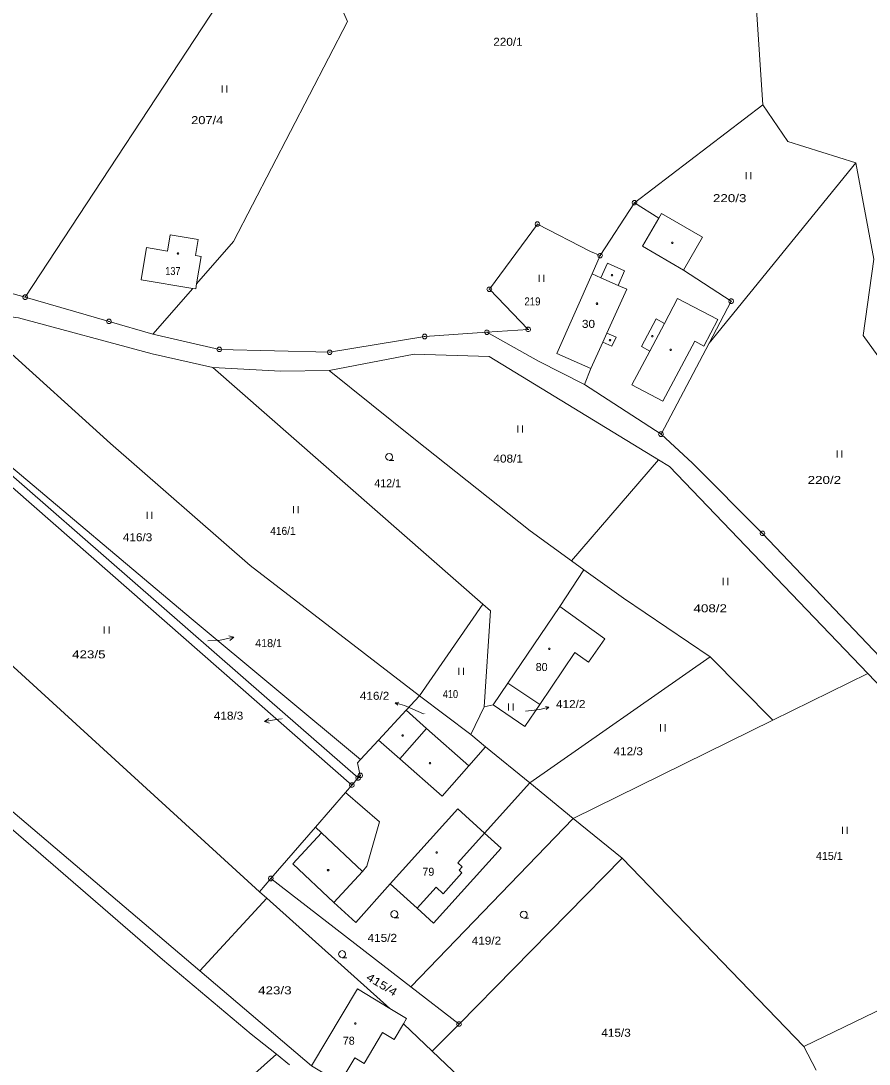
# Model space of a CAD drawing. Extents: x -687390 to -684106, y -954833 to -951648.
# Drawn here: x -686581.3 to -686401.1, y -952815.4 to -952593.8 of the extents above; entities that cross this region are included whole.
import ezdxf
from ezdxf.enums import TextEntityAlignment as Align

# ---------------------------------------------------------------- set-up
doc = ezdxf.new("R2010")
doc.units = 0
doc.header["$LTSCALE"] = 0.68
for name, color, linetype, lineweight in [('1', 7, 'Continuous', 13), ('3', 7, 'Continuous', 13), ('4', 7, 'Continuous', 13), ('5', 7, 'Continuous', 13), ('7', 7, 'Continuous', 13), ('8', 7, 'Continuous', 13)]:
    doc.layers.add(name, color=color, linetype=linetype, lineweight=lineweight)
doc.layers.add('2', color=7, linetype='Continuous')

msp = doc.modelspace()

# ---------------------------------------------------------------- linework, layer by layer
at = {"layer": '1'}
for p, q in [((-686425.13, -952590.27), (-686423.68, -952611.6)), ((-686458.26, -952643.63), (-686450.94, -952632.42)), ((-686445.81, -952635.7), (-686445.22, -952634.68)), ((-686543.98, -952649.65), (-686536.12, -952640.66)), ((-686544.81, -952650.6), (-686553.3, -952660.3)), ((-686580.4, -952652.47), (-686562.6, -952657.61)), ((-686553.3, -952660.3), (-686562.6, -952657.61)), ((-686585.59, -952662.44), (-686562.27, -952683.54)), ((-686435.12, -952662.25), (-686445.31, -952681.57)), ((-686613.19, -952664.18), (-686529.1, -952737.61)), ((-686612.84, -952663.77), (-686545.12, -952720.73)), ((-686540.52, -952667.43), (-686553.46, -952664.51)), ((-686471.33, -952666.06), (-686461.61, -952671.04)), ((-686540.52, -952667.43), (-686526.1, -952668.17)), ((-686515.83, -952668.02), (-686526.1, -952668.17)), ((-686497.82, -952682.47), (-686473.14, -952702.07)), ((-686445.31, -952681.57), (-686438.62, -952687.72)), ((-686532.63, -952709.42), (-686562.27, -952683.54)), ((-686464.34, -952708.44), (-686445.87, -952687)), ((-686423.77, -952702.62), (-686438.62, -952687.72)), ((-686532.63, -952709.42), (-686496.66, -952737.14)), ((-686483.17, -952717.66), (-686496.66, -952737.14)), ((-686466.81, -952718.15), (-686477.84, -952734.42)), ((-686434.87, -952728.81), (-686453.32, -952716.4)), ((-686509.16, -952750.64), (-686545.12, -952720.73)), ((-686530.65, -952778.73), (-686586.94, -952727.34)), ((-686473.17, -952755.63), (-686434.87, -952728.81)), ((-686434.87, -952728.81), (-686421.53, -952742.32)), ((-686480.99, -952739.06), (-686477.84, -952734.42)), ((-686477.84, -952734.42), (-686471.1, -952738.99)), ((-686529.1, -952737.61), (-686509.67, -952754.57)), ((-686496.66, -952737.14), (-686485.74, -952745.37)), ((-686480.99, -952739.06), (-686482.9, -952739.43)), ((-686480.99, -952739.06), (-686474.22, -952743.64)), ((-686471.1, -952738.99), (-686474.22, -952743.64)), ((-686482.58, -952747.94), (-686486.13, -952751.98)), ((-686509.16, -952750.64), (-686509.81, -952751.34)), ((-686509.81, -952751.34), (-686509.21, -952754.04)), ((-686473.17, -952755.63), (-686482.79, -952766.3)), ((-686473.17, -952755.63), (-686463.95, -952763.15)), ((-686518.73, -952765), (-686517.45, -952766.2)), ((-686482.79, -952766.3), (-686479.27, -952769.48)), ((-686488.24, -952806.85), (-686453.59, -952771.6)), ((-686528.22, -952775.93), (-686530.65, -952778.73)), ((-686502.9, -952777.04), (-686497.14, -952782.23)), ((-686543.29, -952795.55), (-686529.07, -952780.13)), ((-686551.22, -952793.14), (-686532.41, -952809.02)), ((-686509.81, -952799.39), (-686519.6, -952815.68)), ((-686502.94, -952803.52), (-686509.81, -952799.39)), ((-686499.36, -952805.67), (-686502.94, -952803.52)), ((-686508.39, -952815.18), (-686504.47, -952808.66)), ((-686504.47, -952808.66), (-686502.03, -952810.12)), ((-686493.92, -952812.62), (-686500.04, -952806.8)), ((-686488.24, -952806.85), (-686493.92, -952812.62)), ((-686527, -952813.23), (-686532.41, -952809.02))]:
    msp.add_line(p, q, dxfattribs=at)
for points in [[(-686492.17, -952518.13), (-686580.4, -952652.47), (-686584.25, -952651.36)], [(-686523.17, -952568.47), (-686511.91, -952593.94), (-686536.12, -952640.66)], [(-686423.68, -952611.6), (-686450.94, -952632.42), (-686445.81, -952635.7)], [(-686423.68, -952611.6), (-686418.34, -952619.37), (-686403.92, -952623.96), (-686435.12, -952662.25)], [(-686368.22, -952739.86), (-686370.22, -952740.18), (-686384.77, -952684.99), (-686402.34, -952660.57), (-686400.1, -952644.41), (-686403.92, -952623.96)], [(-686445.22, -952634.68), (-686436.48, -952639.73), (-686440.52, -952646.7)], [(-686460.29, -952642.79), (-686471.58, -952636.95), (-686481.79, -952650.79), (-686473.54, -952659.31), (-686482.3, -952659.92), (-686471.33, -952666.06)], [(-686459.92, -952647.52), (-686458.26, -952643.63), (-686460.29, -952642.79)], [(-686440.52, -952646.7), (-686430.42, -952653.32), (-686435.12, -952662.25)], [(-686460.21, -952667.64), (-686467.43, -952664.44), (-686459.92, -952647.52)], [(-686593.81, -952655.27), (-686581.83, -952656.84), (-686553.46, -952664.51)], [(-686482.3, -952659.92), (-686495.52, -952660.83), (-686515.72, -952664.17), (-686539.16, -952663.56), (-686553.3, -952660.3)], [(-686481.85, -952665.06), (-686497.79, -952664.59), (-686515.83, -952668.02), (-686497.82, -952682.47)], [(-686511, -952756.1), (-686582.57, -952693.38), (-686614.33, -952665.54)], [(-686443.53, -952688.42), (-686445.87, -952687), (-686481.85, -952665.06)], [(-686540.52, -952667.43), (-686483.17, -952717.66), (-686481.55, -952719.07)], [(-686445.31, -952681.57), (-686461.61, -952671.04), (-686460.21, -952667.64)], [(-686391.72, -952742.47), (-686401.36, -952732.41), (-686443.53, -952688.42)], [(-686473.14, -952702.07), (-686464.34, -952708.44), (-686461.71, -952710.34)], [(-686355.24, -952759), (-686370.29, -952755.14), (-686389.09, -952739.09), (-686423.77, -952702.62)], [(-686652.75, -952706.57), (-686608.8, -952743.34), (-686551.22, -952793.14)], [(-686646.49, -952707.88), (-686543.29, -952795.55), (-686519.6, -952815.68)], [(-686466.81, -952718.15), (-686461.71, -952710.34), (-686453.32, -952716.4)], [(-686481.55, -952719.07), (-686482.9, -952739.43), (-686485.74, -952745.37)], [(-686463.95, -952763.15), (-686421.53, -952742.32), (-686401.36, -952732.41)], [(-686496.66, -952737.14), (-686499.5, -952740.2), (-686505.36, -952746.53), (-686509.16, -952750.64)], [(-686486.13, -952751.98), (-686495.12, -952744.06), (-686499.5, -952740.2)], [(-686485.74, -952745.37), (-686482.58, -952747.94), (-686473.17, -952755.63)], [(-686512.38, -952757.69), (-686511, -952756.1), (-686509.67, -952754.57), (-686509.21, -952754.04)], [(-686512.38, -952757.69), (-686518.73, -952765), (-686528.22, -952775.93)], [(-686498.49, -952798.92), (-686463.95, -952763.15), (-686453.59, -952771.6)], [(-686517.45, -952766.2), (-686523.58, -952772.8), (-686514.82, -952781.04)], [(-686414.98, -952811.6), (-686389.06, -952799.05), (-686381.67, -952786.11), (-686366.08, -952768.4)], [(-686497.14, -952782.23), (-686493.64, -952785.39), (-686479.27, -952769.48)], [(-686453.59, -952771.6), (-686414.98, -952811.6), (-686412.39, -952816.64)], [(-686528.22, -952775.93), (-686498.49, -952798.92), (-686488.24, -952806.85)], [(-686514.82, -952781.04), (-686510.17, -952785.3), (-686502.9, -952777.04)], [(-686530.65, -952778.73), (-686529.07, -952780.13), (-686502.94, -952803.52)], [(-686502.03, -952810.12), (-686500.04, -952806.8), (-686499.36, -952805.67)], [(-686500.04, -952915.93), (-686510.19, -952940.46), (-686533.73, -952896.74), (-686554.09, -952874.42), (-686574.97, -952856.02), (-686527, -952813.23), (-686524.22, -952815.52)], [(-686461.39, -952843.48), (-686465.11, -952839.97), (-686493.92, -952812.62)], [(-686519.6, -952815.68), (-686513.58, -952819.3), (-686510.38, -952813.98), (-686508.39, -952815.18)]]:
    msp.add_lwpolyline(points, dxfattribs=at)
msp.add_lwpolyline([(-686549.58, -952639.2), (-686543.66, -952640.18), (-686544.24, -952643.64), (-686543.04, -952643.84), (-686543.98, -952649.65), (-686544.15, -952650.7), (-686544.81, -952650.6), (-686555.79, -952648.79), (-686554.65, -952641.92), (-686550.16, -952642.66)], close=True, dxfattribs=at)
at = {"layer": '3'}
for p, q in [((-686538.55, -952607.5), (-686538.55, -952609)), ((-686537.55, -952609), (-686537.55, -952607.5)), ((-686427.25, -952625.92), (-686427.25, -952627.42)), ((-686426.25, -952627.42), (-686426.25, -952625.92)), ((-686471.21, -952647.72), (-686471.21, -952649.22)), ((-686470.21, -952649.22), (-686470.21, -952647.72)), ((-686475.76, -952679.73), (-686475.76, -952681.23)), ((-686474.76, -952681.23), (-686474.76, -952679.73)), ((-686407.91, -952685.04), (-686407.91, -952686.54)), ((-686406.91, -952686.54), (-686406.91, -952685.04)), ((-686554.5, -952698.05), (-686554.5, -952699.55)), ((-686553.5, -952699.55), (-686553.5, -952698.05)), ((-686523.43, -952696.86), (-686523.43, -952698.36)), ((-686522.43, -952698.36), (-686522.43, -952696.86)), ((-686432.14, -952712.09), (-686432.14, -952713.59)), ((-686431.14, -952713.59), (-686431.14, -952712.09)), ((-686563.6, -952722.38), (-686563.6, -952723.88)), ((-686562.6, -952723.88), (-686562.6, -952722.38)), ((-686488.31, -952731.19), (-686488.31, -952732.69)), ((-686487.31, -952732.69), (-686487.31, -952731.19)), ((-686477.75, -952738.77), (-686477.75, -952740.27)), ((-686476.75, -952740.27), (-686476.75, -952738.77)), ((-686445.42, -952743.18), (-686445.42, -952744.68)), ((-686444.42, -952744.68), (-686444.42, -952743.18)), ((-686406.75, -952764.94), (-686406.75, -952766.44)), ((-686405.75, -952766.44), (-686405.75, -952764.94))]:
    msp.add_line(p, q, dxfattribs=at)
for points in [[(-686503.08, -952687.11), (-686503.46, -952687.01), (-686503.73, -952686.74), (-686503.83, -952686.37), (-686503.73, -952686), (-686503.46, -952685.73), (-686503.09, -952685.63), (-686502.72, -952685.73), (-686502.45, -952686), (-686502.35, -952686.38), (-686502.45, -952686.76), (-686502.72, -952687.03), (-686503.1, -952687.13), (-686502.1, -952687.13)], [(-686501.97, -952784.23), (-686502.35, -952784.13), (-686502.62, -952783.86), (-686502.72, -952783.49), (-686502.62, -952783.12), (-686502.35, -952782.85), (-686501.98, -952782.75), (-686501.61, -952782.85), (-686501.34, -952783.12), (-686501.24, -952783.5), (-686501.34, -952783.88), (-686501.61, -952784.15), (-686501.99, -952784.25), (-686500.99, -952784.25)], [(-686474.46, -952784.33), (-686474.84, -952784.23), (-686475.11, -952783.96), (-686475.21, -952783.59), (-686475.11, -952783.22), (-686474.84, -952782.95), (-686474.47, -952782.85), (-686474.1, -952782.95), (-686473.83, -952783.22), (-686473.73, -952783.6), (-686473.83, -952783.98), (-686474.1, -952784.25), (-686474.48, -952784.35), (-686473.48, -952784.35)], [(-686513.07, -952792.72), (-686513.45, -952792.62), (-686513.72, -952792.35), (-686513.82, -952791.98), (-686513.72, -952791.61), (-686513.45, -952791.34), (-686513.08, -952791.24), (-686512.71, -952791.34), (-686512.44, -952791.61), (-686512.34, -952791.99), (-686512.44, -952792.37), (-686512.71, -952792.64), (-686513.09, -952792.74), (-686512.09, -952792.74)]]:
    msp.add_lwpolyline(points, dxfattribs=at)
at = {"layer": '4'}
for p, q in [((-686458.09, -952648.34), (-686454.44, -952649.95)), ((-686447.72, -952663.9), (-686444.59, -952658.02)), ((-686456.8, -952660.07), (-686457.66, -952661.99)), ((-686457.66, -952661.99), (-686460.21, -952667.64)), ((-686451.52, -952671.06), (-686444.9, -952674.57)), ((-686457.25, -952725.02), (-686466.81, -952718.15)), ((-686460.7, -952729.99), (-686457.25, -952725.02)), ((-686471.1, -952738.99), (-686463.66, -952727.91)), ((-686463.66, -952727.91), (-686460.7, -952729.99)), ((-686495.12, -952744.06), (-686500.8, -952750.54)), ((-686486.13, -952751.98), (-686491.81, -952758.46)), ((-686505.14, -952763.9), (-686512.38, -952757.69)), ((-686505.14, -952763.9), (-686507.83, -952773.27)), ((-686508.73, -952774.41), (-686517.45, -952766.2)), ((-686488.47, -952772.61), (-686482.79, -952766.3)), ((-686508.73, -952774.41), (-686507.83, -952773.27)), ((-686514.82, -952781.04), (-686508.73, -952774.41))]:
    msp.add_line(p, q, dxfattribs=at)
for points in [[(-686440.52, -952646.7), (-686449.26, -952641.65), (-686445.81, -952635.7)], [(-686459.92, -952647.52), (-686458.09, -952648.34), (-686456.72, -952645.24), (-686453.07, -952646.86), (-686454.44, -952649.95), (-686452.61, -952650.78)], [(-686457.66, -952661.99), (-686455.74, -952662.86), (-686454.87, -952660.93), (-686456.8, -952660.07), (-686452.61, -952650.78)], [(-686451.52, -952671.06), (-686447.72, -952663.9), (-686449.5, -952662.97), (-686446.36, -952657.07), (-686444.59, -952658.02), (-686441.79, -952652.71), (-686433.25, -952657.23), (-686436.22, -952662.83), (-686438.16, -952661.8), (-686444.9, -952674.57)], [(-686491.81, -952758.46), (-686500.8, -952750.54), (-686505.36, -952746.53)], [(-686502.9, -952777.04), (-686488.52, -952761.12), (-686482.79, -952766.3)], [(-686497.14, -952782.23), (-686493.11, -952777.79), (-686491.61, -952779.15), (-686487.62, -952774.72), (-686488.21, -952774.18), (-686487.55, -952773.45), (-686488.47, -952772.61)]]:
    msp.add_lwpolyline(points, dxfattribs=at)
at = {"layer": '5'}
for points in [[(-686442.84, -952640.76), (-686442.75, -952640.91), (-686442.84, -952641.06), (-686443.02, -952641.06), (-686443.11, -952640.91), (-686443.02, -952640.76)], [(-686547.83, -952643.01), (-686547.74, -952643.16), (-686547.83, -952643.31), (-686548.01, -952643.31), (-686548.1, -952643.16), (-686548.01, -952643.01)], [(-686455.66, -952647.66), (-686455.57, -952647.81), (-686455.66, -952647.96), (-686455.84, -952647.96), (-686455.93, -952647.81), (-686455.84, -952647.66)], [(-686458.85, -952653.69), (-686458.76, -952653.84), (-686458.85, -952653.99), (-686459.03, -952653.99), (-686459.12, -952653.84), (-686459.03, -952653.69)], [(-686456.09, -952661.44), (-686456, -952661.59), (-686456.09, -952661.74), (-686456.27, -952661.74), (-686456.36, -952661.59), (-686456.27, -952661.44)], [(-686447.08, -952660.57), (-686446.99, -952660.72), (-686447.08, -952660.87), (-686447.26, -952660.87), (-686447.35, -952660.72), (-686447.26, -952660.57)], [(-686443.16, -952663.48), (-686443.07, -952663.63), (-686443.16, -952663.78), (-686443.34, -952663.78), (-686443.43, -952663.63), (-686443.34, -952663.48)], [(-686468.94, -952726.97), (-686468.85, -952727.12), (-686468.94, -952727.27), (-686469.12, -952727.27), (-686469.21, -952727.12), (-686469.12, -952726.97)], [(-686500.09, -952745.4), (-686500, -952745.55), (-686500.09, -952745.7), (-686500.27, -952745.7), (-686500.36, -952745.55), (-686500.27, -952745.4)], [(-686494.3, -952751.26), (-686494.21, -952751.41), (-686494.3, -952751.56), (-686494.48, -952751.56), (-686494.57, -952751.41), (-686494.48, -952751.26)], [(-686492.89, -952770.27), (-686492.8, -952770.42), (-686492.89, -952770.57), (-686493.07, -952770.57), (-686493.16, -952770.42), (-686493.07, -952770.27)], [(-686515.95, -952774.02), (-686515.86, -952774.17), (-686515.95, -952774.32), (-686516.13, -952774.32), (-686516.22, -952774.17), (-686516.13, -952774.02)], [(-686510.17, -952806.55), (-686510.08, -952806.7), (-686510.17, -952806.85), (-686510.35, -952806.85), (-686510.44, -952806.7), (-686510.35, -952806.55)]]:
    msp.add_lwpolyline(points, close=True, dxfattribs=at)
at = {"layer": '7'}
for p, q in [((-686536.05, -952724.692), (-686538.99, -952725.29)), ((-686541.63, -952725.45), (-686538.99, -952725.29)), ((-686501.776, -952738.638), (-686499.84, -952739.18)), ((-686495.78, -952740.96), (-686499.84, -952739.18)), ((-686474.13, -952740.37), (-686471.1, -952740.04)), ((-686469.152, -952739.545), (-686471.1, -952740.04)), ((-686529.558, -952742.608), (-686526.61, -952742.05)), ((-686525.92, -952742.02), (-686526.62, -952742.05))]:
    msp.add_line(p, q, dxfattribs=at)
for points in [[(-686537.13, -952724.401), (-686536.05, -952724.692), (-686536.93, -952725.381)], [(-686501.221, -952739.142), (-686501.776, -952738.638), (-686501.04, -952738.496)], [(-686469.884, -952739.386), (-686469.152, -952739.545), (-686469.719, -952740.035)], [(-686528.482, -952742.913), (-686529.558, -952742.608), (-686528.668, -952741.931)]]:
    msp.add_lwpolyline(points, dxfattribs=at)
at = {"layer": '8'}
for p, q in [((-686451.06, -952632.42), (-686450.82, -952632.42)), ((-686471.7, -952636.95), (-686471.46, -952636.95)), ((-686458.38, -952643.63), (-686458.14, -952643.63)), ((-686481.91, -952650.79), (-686481.67, -952650.79)), ((-686580.52, -952652.47), (-686580.28, -952652.47)), ((-686430.54, -952653.32), (-686430.3, -952653.32)), ((-686562.72, -952657.61), (-686562.48, -952657.61)), ((-686482.42, -952659.92), (-686482.18, -952659.92)), ((-686473.66, -952659.31), (-686473.42, -952659.31)), ((-686495.64, -952660.83), (-686495.4, -952660.83)), ((-686539.28, -952663.56), (-686539.04, -952663.56)), ((-686515.84, -952664.17), (-686515.6, -952664.17)), ((-686445.43, -952681.57), (-686445.19, -952681.57)), ((-686423.89, -952702.62), (-686423.65, -952702.62)), ((-686509.79, -952754.57), (-686509.55, -952754.57)), ((-686509.33, -952754.04), (-686509.09, -952754.04)), ((-686511.12, -952756.1), (-686510.88, -952756.1)), ((-686528.34, -952775.93), (-686528.1, -952775.93)), ((-686488.36, -952806.85), (-686488.12, -952806.85))]:
    msp.add_line(p, q, dxfattribs=at)
for points in [[(-686450.79, -952631.94), (-686450.54, -952632.12), (-686450.44, -952632.41), (-686450.54, -952632.7), (-686450.79, -952632.88), (-686451.1, -952632.88), (-686451.35, -952632.7), (-686451.45, -952632.41), (-686451.35, -952632.12), (-686451.1, -952631.94)], [(-686471.43, -952636.47), (-686471.18, -952636.65), (-686471.08, -952636.94), (-686471.18, -952637.23), (-686471.43, -952637.41), (-686471.74, -952637.41), (-686471.99, -952637.23), (-686472.09, -952636.94), (-686471.99, -952636.65), (-686471.74, -952636.47)], [(-686458.11, -952643.15), (-686457.86, -952643.33), (-686457.76, -952643.62), (-686457.86, -952643.91), (-686458.11, -952644.09), (-686458.42, -952644.09), (-686458.67, -952643.91), (-686458.77, -952643.62), (-686458.67, -952643.33), (-686458.42, -952643.15)], [(-686481.64, -952650.31), (-686481.39, -952650.49), (-686481.29, -952650.78), (-686481.39, -952651.07), (-686481.64, -952651.25), (-686481.95, -952651.25), (-686482.2, -952651.07), (-686482.3, -952650.78), (-686482.2, -952650.49), (-686481.95, -952650.31)], [(-686580.25, -952651.99), (-686580, -952652.17), (-686579.9, -952652.46), (-686580, -952652.75), (-686580.25, -952652.93), (-686580.56, -952652.93), (-686580.81, -952652.75), (-686580.91, -952652.46), (-686580.81, -952652.17), (-686580.56, -952651.99)], [(-686430.27, -952652.84), (-686430.02, -952653.02), (-686429.92, -952653.31), (-686430.02, -952653.6), (-686430.27, -952653.78), (-686430.58, -952653.78), (-686430.83, -952653.6), (-686430.93, -952653.31), (-686430.83, -952653.02), (-686430.58, -952652.84)], [(-686562.45, -952657.13), (-686562.2, -952657.31), (-686562.1, -952657.6), (-686562.2, -952657.89), (-686562.45, -952658.07), (-686562.76, -952658.07), (-686563.01, -952657.89), (-686563.11, -952657.6), (-686563.01, -952657.31), (-686562.76, -952657.13)], [(-686495.37, -952660.35), (-686495.12, -952660.53), (-686495.02, -952660.82), (-686495.12, -952661.11), (-686495.37, -952661.29), (-686495.68, -952661.29), (-686495.93, -952661.11), (-686496.03, -952660.82), (-686495.93, -952660.53), (-686495.68, -952660.35)], [(-686482.15, -952659.44), (-686481.9, -952659.62), (-686481.8, -952659.91), (-686481.9, -952660.2), (-686482.15, -952660.38), (-686482.46, -952660.38), (-686482.71, -952660.2), (-686482.81, -952659.91), (-686482.71, -952659.62), (-686482.46, -952659.44)], [(-686473.39, -952658.83), (-686473.14, -952659.01), (-686473.04, -952659.3), (-686473.14, -952659.59), (-686473.39, -952659.77), (-686473.7, -952659.77), (-686473.95, -952659.59), (-686474.05, -952659.3), (-686473.95, -952659.01), (-686473.7, -952658.83)], [(-686539.01, -952663.08), (-686538.76, -952663.26), (-686538.66, -952663.55), (-686538.76, -952663.84), (-686539.01, -952664.02), (-686539.32, -952664.02), (-686539.57, -952663.84), (-686539.67, -952663.55), (-686539.57, -952663.26), (-686539.32, -952663.08)], [(-686515.57, -952663.69), (-686515.32, -952663.87), (-686515.22, -952664.16), (-686515.32, -952664.45), (-686515.57, -952664.63), (-686515.88, -952664.63), (-686516.13, -952664.45), (-686516.23, -952664.16), (-686516.13, -952663.87), (-686515.88, -952663.69)], [(-686445.16, -952681.09), (-686444.91, -952681.27), (-686444.81, -952681.56), (-686444.91, -952681.85), (-686445.16, -952682.03), (-686445.47, -952682.03), (-686445.72, -952681.85), (-686445.82, -952681.56), (-686445.72, -952681.27), (-686445.47, -952681.09)], [(-686423.62, -952702.14), (-686423.37, -952702.32), (-686423.27, -952702.61), (-686423.37, -952702.9), (-686423.62, -952703.08), (-686423.93, -952703.08), (-686424.18, -952702.9), (-686424.28, -952702.61), (-686424.18, -952702.32), (-686423.93, -952702.14)], [(-686509.06, -952753.56), (-686508.81, -952753.74), (-686508.71, -952754.03), (-686508.81, -952754.32), (-686509.06, -952754.5), (-686509.37, -952754.5), (-686509.62, -952754.32), (-686509.72, -952754.03), (-686509.62, -952753.74), (-686509.37, -952753.56)], [(-686510.85, -952755.62), (-686510.6, -952755.8), (-686510.5, -952756.09), (-686510.6, -952756.38), (-686510.85, -952756.56), (-686511.16, -952756.56), (-686511.41, -952756.38), (-686511.51, -952756.09), (-686511.41, -952755.8), (-686511.16, -952755.62)], [(-686509.52, -952754.09), (-686509.27, -952754.27), (-686509.17, -952754.56), (-686509.27, -952754.85), (-686509.52, -952755.03), (-686509.83, -952755.03), (-686510.08, -952754.85), (-686510.18, -952754.56), (-686510.08, -952754.27), (-686509.83, -952754.09)], [(-686528.07, -952775.45), (-686527.82, -952775.63), (-686527.72, -952775.92), (-686527.82, -952776.21), (-686528.07, -952776.39), (-686528.38, -952776.39), (-686528.63, -952776.21), (-686528.73, -952775.92), (-686528.63, -952775.63), (-686528.38, -952775.45)], [(-686488.09, -952806.37), (-686487.84, -952806.55), (-686487.74, -952806.84), (-686487.84, -952807.13), (-686488.09, -952807.31), (-686488.4, -952807.31), (-686488.65, -952807.13), (-686488.75, -952806.84), (-686488.65, -952806.55), (-686488.4, -952806.37)]]:
    msp.add_lwpolyline(points, close=True, dxfattribs=at)

# ---------------------------------------------------------------- texts
at = {"layer": '2'}
for s, height, width, p in [('220/1', 1.7, 1.1, (-686480.965, -952599.07)), ('207/4', 1.7, 1.2, (-686545.145, -952615.71)), ('220/3', 1.7, 1.25, (-686434.285, -952632.28)), ('137', 1.7, 0.85, (-686550.645, -952647.76)), ('219', 1.7, 0.9, (-686474.345, -952654.21)), ('30', 1.7, 1.1, (-686462.125, -952658.98)), ('408/1', 1.7, 1.1, (-686480.925, -952687.59)), ('220/2', 1.7, 1.25, (-686414.165, -952692.13)), ('416/3', 1.7, 1.1, (-686559.665, -952704.3)), ('416/1', 1.7, 0.95, (-686528.345, -952702.95)), ('408/2', 1.7, 1.25, (-686438.415, -952719.39)), ('423/5', 1.7, 1.25, (-686570.445, -952729.17)), ('410', 1.7, 0.85, (-686491.665, -952737.6)), ('412/2', 0.1, 1.1, (-686474.102, -952740.37)), ('418/3', 0.1, 1.1, (-686525.892, -952742.02)), ('416/2', 0.1, 1.1, (-686495.752, -952740.96)), ('412/3', 1.7, 1.1, (-686455.415, -952749.75)), ('415/2', 1.7, 1.1, (-686507.665, -952789.38)), ('419/2', 1.7, 1.1, (-686485.545, -952789.97)), ('423/3', 1.7, 1.25, (-686530.925, -952800.53)), ('415/3', 1.7, 1.1, (-686458.005, -952809.53))]:
    msp.add_text(s, height=height, dxfattribs=dict(at, width=width)).set_placement(p)
for s, height, p in [('412/1', 1.7, (-686506.245, -952692.83)), ('418/1', 0.1, (-686541.602, -952725.45)), ('80', 1.7, (-686471.945, -952731.86)), ('415/1', 1.7, (-686412.405, -952771.98)), ('79', 1.7, (-686496.015, -952775.34)), ('78', 1.7, (-686512.935, -952811.22))]:
    msp.add_text(s, height=height, dxfattribs=at).set_placement(p)
at = {"layer": '2', "width": 1.25}
msp.add_text('415/4', height=1.7, rotation=329.164, dxfattribs=at).set_placement((-686508.122, -952797.353))
at = {"layer": '7'}
msp.add_text('418/1', height=1.7, dxfattribs=at).set_placement((-686531.535, -952726.78))
at = {"layer": '7', "width": 1.1}
for s, p in [('416/2', (-686503.056, -952737.97)), ('418/3', (-686534.076, -952742.19))]:
    msp.add_text(s, height=1.7, dxfattribs=at).set_placement(p, align=Align.RIGHT)
msp.add_text('412/2', height=1.7, dxfattribs=at).set_placement((-686467.635, -952739.72))

doc.saveas('drawing.dxf')
